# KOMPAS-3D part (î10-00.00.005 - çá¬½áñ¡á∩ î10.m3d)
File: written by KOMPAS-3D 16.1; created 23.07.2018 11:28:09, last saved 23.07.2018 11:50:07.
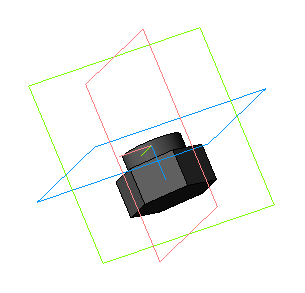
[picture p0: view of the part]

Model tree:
1. Эскиз:1
2. Операция выдавливания:1
     Расстояние 1 = 15
3. Эскиз:2
4. Вырезать элемент выдавливания:1  (labels: Сталь 12Х18Н10Т ГОСТ 5632-72)
     Расстояние 1 = 5

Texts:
  Закладная М10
